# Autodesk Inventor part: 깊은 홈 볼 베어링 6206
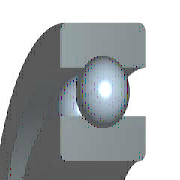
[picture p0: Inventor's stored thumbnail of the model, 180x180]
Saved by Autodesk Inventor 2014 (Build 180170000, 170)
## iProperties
IsCustomPart: 1
Created: 2012-02
Part Number: 깊은 홈 볼 베어링 6206
Material: 강철, 연강
Description: 깊은 그루부 볼 베어링
Document SubType Name: Modeling
Standard: JIS B 1521
Designer: mdu-01
Standards Organization: JIS
Language: ko-KR
Size Designation: 6206 30x62x16
Categories: <MemberInstance><Categories><Category DisplayName="샤프트 부품" InternalName="7f7aeb1f-a693-4053-b835-cee3144e0d98" Mnemonic="SHFT"><Category DisplayName="베어링" Inter
Density: 1 g/cm^3
Appearance: 강철(1)
Author: mdu-01
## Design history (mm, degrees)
sketch "스케치" dims "d0" = 8.32 (= -0.26 x WD + 0.26 x BD)
  geometry: L1 (3.84, 23)-(12.16, 23); L2 (8, 23)-(8, 18.84); L3 (8, 23)-(8, 27.16); L4 (4.909, 20.216)-(0, 20.216); L5 (0, 15)-(16, 15); L6 (4.909, 25.784)-(0, 25.784); L7 (0, 31)-(16, 31); L8 (16, 15)-(16, 20.216); L9 (11.091, 20.216)-(16, 20.216); L10 (11.091, 25.784)-(16, 25.784); L11 (16, 31)-(16, 25.784); L12 (-1.4, 0)-(8.4, 0) reference; L13 (0, -0.3)-(0, 5.3) reference
  constraints: 22 end point, 4 point on line, 2 collinear, 2 perpendicular, 2 symmetric about line, 1 midpoint, 1 parallel, 14 other
  dimensions: "d9" = 30 diameter of L5 L12 (= WD); "d11" = 62 diameter of L7 L12 (= BD); "d12" = 16 distance between parallel lines of L8 L13 (= KB); "d13" = 40.432 diameter of L9 L12 (= 0.326 x BD + 0.674 x WD)
revolve "본체" stored, may be unused: angle "d6" = 90 deg
revolve "볼" stored, may be unused: angle "d7" = 90 deg
pattern_circular "IDS_ARRAYBALL[SIMPL:T]" dims angle "d3" = 360 deg
body "Solid1"
fillet "모깎기1" dims "d1" = 1 (= KRS)
other parameters: "WD" = 30 [user parameter; used in 5 equation terms], "BD" = 62 [user parameter; used in 5 equation terms], "KB" = 16 [user parameter; used in 1 equation term], "KRS" = 1 [user parameter; used in 1 equation term], "d4" = 0, "d5" = 0, "d8" = 0, "d14" = 0, "d15" = 0, "BBA" = 0 [user parameter], "BC0" = 1.12e+07 [user parameter], "BC" = 1.95e+07 [user parameter], "BR" = 31 (= 0.5 x BD) [user parameter], "WR" = 15 (= 0.5 x WD) [user parameter]
